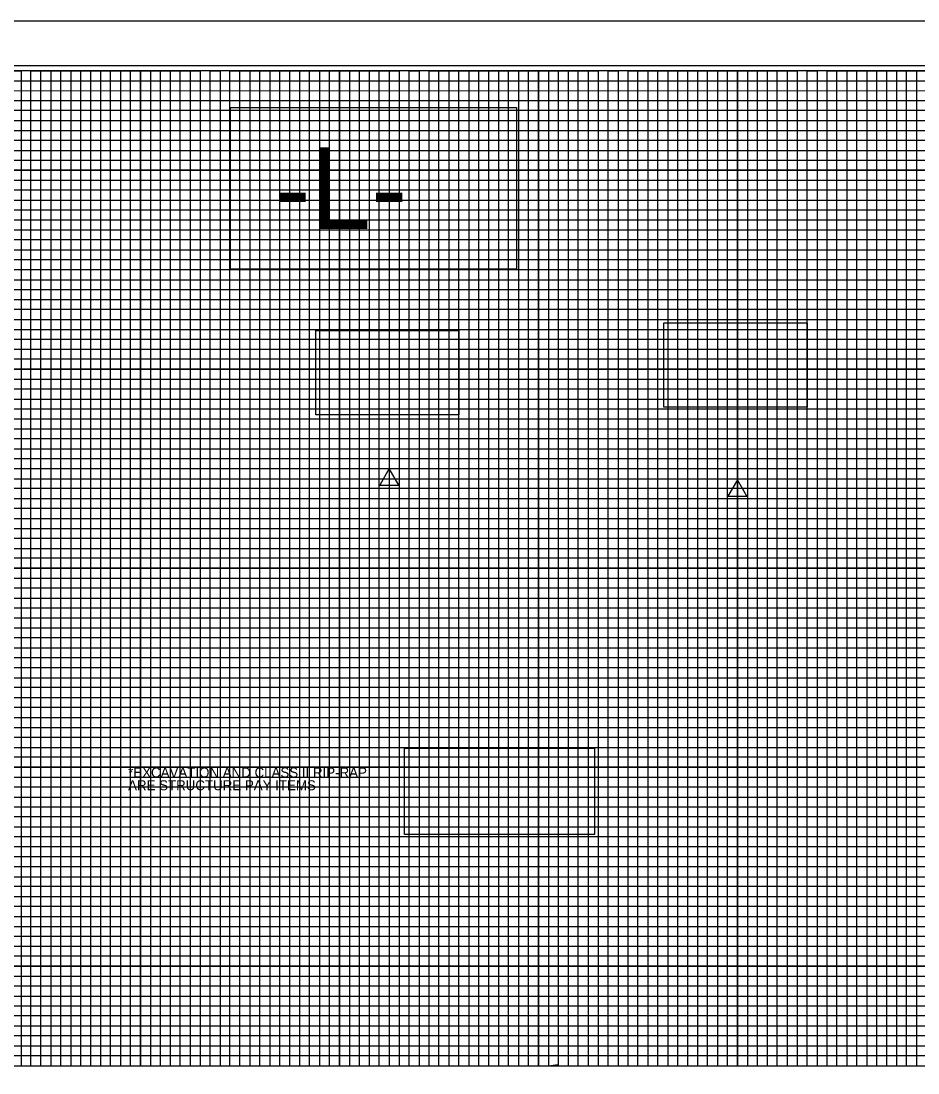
# Model space of a CAD drawing. Extents: x 1019474 to 1021161, y 504129 to 505324.
# Drawn here: x 1020231 to 1020682, y 504701 to 505229 of the extents above; entities that cross this region are included whole.
import ezdxf

# ---------------------------------------------------------------- set-up
doc = ezdxf.new("R2010")
doc.units = 0
for name, color, linetype in [('Default', 7, 'Continuous'), ('Prop Grid Mask', 7, 'Continuous'), ('Prop Vertical Profile Curve Label', 7, 'Continuous'), ('Prop VPI Label', 7, 'Continuous'), ('Sheet Cutting Line CELL', 7, 'Continuous'), ('Sheet DOT Grid CELL', 7, 'Continuous'), ('Sheet Layout Profile Border Port 1', 7, 'Continuous'), ('Sheet Plot Border Inside CELL', 7, 'Continuous'), ('Sheet Plot Border Outside CELL', 7, 'Continuous'), ('Sheet Profile CELL', 7, 'Continuous'), ('Sheet Profile Grid Major CELL', 7, 'Continuous'), ('Sheet Profile Grid Middle CELL', 7, 'Continuous'), ('Sheet Profile Grid Minor CELL', 7, 'Continuous')]:
    doc.layers.add(name, color=color, linetype=linetype)

msp = doc.modelspace()

# ---------------------------------------------------------------- linework, layer by layer
at = {"layer": 'Prop Grid Mask'}
for points in [[(1020336.48, 505185.85), (1020480.21, 505185.85), (1020480.21, 505104.52), (1020336.48, 505104.52)], [(1020554.29, 505077.6), (1020626.17, 505077.6), (1020626.17, 505035.2), (1020554.29, 505035.2)], [(1020379.39, 505073.78), (1020451.27, 505073.78), (1020451.27, 505031.38), (1020379.39, 505031.38)], [(1020423.98, 504863.83), (1020519.35, 504863.83), (1020519.35, 504820.42), (1020423.98, 504820.42)]]:
    msp.add_lwpolyline(points, close=True, dxfattribs=at)
at = {"layer": 'Prop Vertical Profile Curve Label'}
for points in [[(1020411.46, 504996.11), (1020420.98, 504996.11), (1020416.22, 505004.36)], [(1020586.46, 504990.55), (1020595.98, 504990.55), (1020591.22, 504998.8)]]:
    msp.add_lwpolyline(points, close=True, dxfattribs=at)
at = {"layer": 'Sheet Cutting Line CELL'}
msp.add_line((1021158.22, 505229.29), (1019474.22, 505229.29), dxfattribs=at)
at = {"layer": 'Sheet DOT Grid CELL'}
for p, q in [((1020241.22, 504704.29), (1020241.22, 505204.29)), ((1020291.22, 504704.29), (1020291.22, 505204.29)), ((1020341.22, 504704.29), (1020341.22, 505204.29)), ((1020391.22, 504704.29), (1020391.22, 505204.29)), ((1020441.22, 504704.29), (1020441.22, 505204.29)), ((1020491.22, 504704.29), (1020491.22, 505204.29)), ((1020541.22, 504704.29), (1020541.22, 505204.29)), ((1020591.22, 504704.29), (1020591.22, 505204.29)), ((1020641.22, 504704.29), (1020641.22, 505204.29)), ((1020941.17, 505154.29), (1019641.22, 505154.29)), ((1020941.17, 505104.29), (1019641.22, 505104.29)), ((1020941.22, 505054.29), (1019641.22, 505054.29)), ((1021141.22, 505004.29), (1019641.22, 505004.29)), ((1021141.22, 504954.29), (1019641.22, 504954.29)), ((1021141.22, 504904.29), (1019641.22, 504904.29)), ((1021141.22, 504854.29), (1019641.22, 504854.29)), ((1021141.22, 504804.29), (1019641.22, 504804.29)), ((1021141.22, 504754.29), (1019641.22, 504754.29))]:
    msp.add_line(p, q, dxfattribs=at)
at = {"layer": 'Sheet Layout Profile Border Port 1'}
msp.add_lwpolyline([(1019691.22, 505043.24), (1019691.22, 504704.29), (1021091.22, 504704.29), (1021091.22, 505043.24)], dxfattribs=at)
at = {"layer": 'Sheet Plot Border Inside CELL'}
msp.add_lwpolyline([(1019487.22, 504151.74), (1021153.72, 504151.74), (1021153.72, 505206.84), (1019487.22, 505206.84)], close=True, dxfattribs=at)
at = {"layer": 'Sheet Plot Border Outside CELL'}
msp.add_lwpolyline([(1019474.22, 504129.29), (1021158.22, 504129.29), (1021158.22, 505229.29), (1019474.22, 505229.29)], close=True, dxfattribs=at)
at = {"layer": 'Sheet Profile CELL'}
msp.add_line((1019641.22, 504704.29), (1021141.22, 504704.29), dxfattribs=at)
msp.add_lwpolyline([(1021141.22, 505204.29), (1019641.22, 505204.29), (1019641.22, 504154.29), (1021141.22, 504154.29)], close=True, dxfattribs=at)
at = {"layer": 'Sheet Profile Grid Major CELL'}
for points in [[(1020191.22, 504704.29), (1020241.22, 504704.29), (1020241.22, 505204.29), (1020291.22, 505204.29), (1020291.22, 504704.29), (1020341.22, 504704.29), (1020341.22, 505204.29), (1020391.22, 505204.29), (1020391.22, 504704.29), (1020441.22, 504704.29), (1020441.22, 505204.29), (1020491.22, 505204.29), (1020491.22, 504704.29), (1020541.22, 504704.29), (1020541.22, 505204.29), (1020591.22, 505204.29), (1020591.22, 504704.29), (1020641.22, 504704.29), (1020641.22, 505204.29), (1020691.22, 505204.29)], [(1019641.22, 505154.29), (1020941.22, 505154.29)], [(1020941.22, 505104.29), (1019641.22, 505104.29), (1019641.22, 505054.29), (1020941.22, 505054.29)], [(1021141.22, 505004.29), (1019641.22, 505004.29), (1019641.22, 504954.29), (1021141.22, 504954.29)], [(1021141.22, 504904.29), (1019641.22, 504904.29), (1019641.22, 504854.29), (1021141.22, 504854.29)], [(1021141.22, 504804.29), (1019641.22, 504804.29), (1019641.22, 504804.29), (1019641.22, 504754.29), (1021141.22, 504754.29)]]:
    msp.add_lwpolyline(points, dxfattribs=at)
at = {"layer": 'Sheet Profile Grid Middle CELL'}
msp.add_line((1019641.22, 505179.29), (1020941.17, 505179.29), dxfattribs=at)
for points in [[(1020216.22, 504704.29), (1020266.22, 504704.29), (1020266.22, 504704.29), (1020266.22, 505204.29), (1020316.22, 505204.29), (1020316.22, 504704.29), (1020366.22, 504704.29), (1020366.22, 505204.29), (1020416.22, 505204.29), (1020416.22, 504704.29), (1020466.22, 504704.29), (1020466.22, 505204.29), (1020516.22, 505204.29), (1020516.22, 504704.29), (1020566.22, 504704.29), (1020566.22, 505204.29), (1020616.22, 505204.29), (1020616.22, 504704.29), (1020666.22, 504704.29), (1020666.22, 505204.29), (1020716.22, 505204.29)], [(1020941.22, 505129.29), (1019641.22, 505129.29), (1019641.22, 505079.29), (1020941.22, 505079.29)], [(1021141.22, 505029.29), (1019641.22, 505029.29), (1019641.22, 504979.29), (1020966.22, 504979.29)], [(1021141.22, 504929.29), (1019641.22, 504929.29), (1019641.22, 504879.29), (1021141.22, 504879.29)], [(1021141.22, 504829.29), (1019641.22, 504829.29), (1019641.22, 504779.29), (1021141.22, 504779.29)], [(1021141.22, 504729.29), (1019641.22, 504729.29)]]:
    msp.add_lwpolyline(points, dxfattribs=at)
at = {"layer": 'Sheet Profile Grid Minor CELL'}
for p, q in [((1019691.22, 505199.29), (1020941.22, 505199.29)), ((1020941.22, 505194.29), (1019691.22, 505193.94)), ((1019691.22, 505189.29), (1020941.22, 505189.29)), ((1020941.17, 505069.29), (1019691.22, 505069.29)), ((1020941.22, 505064.29), (1019691.22, 505064.29)), ((1020941.22, 505059.29), (1019691.22, 505059.29)), ((1019691.22, 505049.29), (1020941.22, 505049.29)), ((1020941.22, 505044.29), (1019691.22, 505044.29)), ((1019691.22, 505039.29), (1021091.22, 505039.29)), ((1021091.22, 505019.29), (1019691.22, 505019.29)), ((1019691.22, 505014.29), (1021091.22, 505014.29)), ((1021091.22, 504994.29), (1019691.22, 504994.29)), ((1019691.22, 504989.29), (1021091.22, 504989.29)), ((1021091.22, 504969.29), (1019691.22, 504969.29)), ((1019691.22, 504964.29), (1021091.22, 504964.29)), ((1021091.22, 504959.29), (1019691.22, 504959.29)), ((1019691.22, 504949.29), (1021091.22, 504949.29)), ((1021091.22, 504944.29), (1019691.22, 504944.29)), ((1019691.22, 504939.29), (1021091.22, 504939.29)), ((1021091.22, 504934.29), (1019691.22, 504934.29)), ((1019691.22, 504924.29), (1021091.22, 504924.29)), ((1021091.22, 504919.29), (1019691.22, 504919.29)), ((1019691.22, 504914.29), (1021091.22, 504914.29)), ((1021091.22, 504909.29), (1019691.22, 504909.29)), ((1019691.22, 504899.29), (1021091.22, 504899.29)), ((1021091.22, 504894.29), (1019691.22, 504894.29)), ((1019691.22, 504889.29), (1021091.22, 504889.29)), ((1021091.22, 504884.29), (1019691.22, 504884.29)), ((1019691.22, 504874.29), (1021091.22, 504874.29)), ((1021091.22, 504869.29), (1019691.22, 504869.29)), ((1019691.22, 504864.29), (1021091.22, 504864.29)), ((1021091.22, 504859.29), (1019691.22, 504859.29)), ((1019691.22, 504849.29), (1021091.22, 504849.29)), ((1021091.22, 504844.29), (1019691.22, 504844.29)), ((1019691.22, 504839.29), (1021091.22, 504839.29)), ((1021091.22, 504834.29), (1019691.22, 504834.29)), ((1019691.22, 504824.29), (1021091.22, 504824.29)), ((1021091.22, 504819.29), (1019691.22, 504819.29)), ((1021091.22, 504814.29), (1019691.22, 504814.29)), ((1021091.22, 504809.29), (1019691.22, 504809.29)), ((1019691.22, 504799.29), (1021091.22, 504799.29)), ((1021091.22, 504794.29), (1019691.22, 504794.29)), ((1019691.22, 504789.29), (1021091.22, 504789.29)), ((1021091.22, 504784.29), (1019691.22, 504784.29)), ((1019691.22, 504774.29), (1021091.22, 504774.29)), ((1021091.22, 504769.29), (1019691.22, 504769.29)), ((1019691.22, 504764.29), (1021091.22, 504764.29)), ((1021091.22, 504759.29), (1019691.22, 504759.29)), ((1019691.22, 504749.29), (1021091.22, 504749.29)), ((1021091.22, 504744.29), (1019691.22, 504744.29)), ((1019691.22, 504739.29), (1021091.22, 504739.29)), ((1021091.22, 504734.29), (1019691.22, 504734.29)), ((1019691.22, 504724.29), (1021091.22, 504724.29)), ((1021091.22, 504719.29), (1019691.22, 504719.29)), ((1019691.22, 504714.29), (1021091.22, 504714.29))]:
    msp.add_line(p, q, dxfattribs=at)
for points in [[(1020226.22, 505204.29), (1020231.22, 505204.29), (1020231.22, 504704.29), (1020236.22, 504704.29), (1020236.22, 505204.29), (1020246.22, 505204.29), (1020246.22, 504704.29), (1020251.22, 504704.29), (1020251.22, 505204.29), (1020256.22, 505204.29), (1020256.22, 504704.29), (1020261.22, 504704.29), (1020261.22, 505204.29), (1020271.22, 505204.29), (1020271.22, 504704.29), (1020276.22, 504704.29), (1020276.22, 505204.29), (1020281.22, 505204.29), (1020281.22, 504704.29), (1020286.22, 504704.29), (1020286.22, 505204.29), (1020296.22, 505204.29), (1020296.22, 504704.29), (1020301.22, 504704.29), (1020301.22, 505204.29), (1020306.22, 505204.29), (1020306.22, 504704.29), (1020311.22, 504704.29), (1020311.22, 505204.29), (1020321.22, 505204.29), (1020321.22, 504704.29), (1020326.22, 504704.29), (1020326.22, 505204.29), (1020331.22, 505204.29), (1020331.22, 504704.29), (1020336.22, 504704.29), (1020336.22, 505204.29), (1020346.22, 505204.29), (1020346.22, 504704.29), (1020346.22, 504704.29), (1020351.22, 504704.29), (1020351.22, 505204.29), (1020356.22, 505204.29), (1020356.22, 504704.29), (1020361.22, 504704.29), (1020361.22, 505204.29), (1020371.22, 505204.29), (1020371.22, 504704.29), (1020376.22, 504704.29), (1020376.22, 505204.29), (1020381.22, 505204.29), (1020381.22, 504704.29), (1020386.22, 504704.29), (1020386.22, 505204.29), (1020396.22, 505204.29), (1020396.22, 504704.29), (1020401.22, 504704.29), (1020401.22, 505204.29), (1020406.22, 505204.29), (1020406.22, 504704.29), (1020411.22, 504704.29), (1020411.22, 505204.29), (1020421.22, 505204.29), (1020421.22, 504704.29), (1020426.22, 504704.29), (1020426.22, 505204.29), (1020431.22, 505204.29), (1020431.22, 504704.29), (1020436.22, 504704.29), (1020436.22, 505204.29), (1020446.22, 505204.29), (1020446.22, 504704.29), (1020451.22, 504704.29), (1020451.22, 505204.29), (1020456.22, 505204.29), (1020456.22, 504704.29), (1020461.22, 504704.29), (1020461.22, 505204.29), (1020471.22, 505204.29), (1020471.22, 504704.29), (1020476.22, 504704.29), (1020476.22, 505204.29), (1020481.22, 505204.29), (1020481.22, 504704.29), (1020486.22, 504704.29), (1020486.22, 505204.29), (1020496.22, 505204.29), (1020496.22, 504704.29), (1020500.92, 504704.84), (1020501.22, 504704.29), (1020501.22, 505204.29), (1020506.22, 505204.29), (1020506.22, 504704.29), (1020511.22, 504704.29), (1020511.22, 505204.29), (1020521.22, 505204.29), (1020521.22, 504704.29), (1020526.22, 504704.29)], [(1020526.22, 504704.29), (1020526.22, 505204.29), (1020531.22, 505204.29), (1020531.22, 504704.29), (1020536.22, 504704.29), (1020536.22, 505204.29), (1020546.22, 505204.29), (1020546.22, 504704.29), (1020551.22, 504704.29), (1020551.22, 505204.29), (1020556.22, 505204.29), (1020556.22, 504704.29), (1020561.22, 504704.29), (1020561.22, 505204.29), (1020571.22, 505204.29), (1020571.22, 504704.29), (1020576.22, 504704.29), (1020576.22, 505204.29), (1020581.22, 505204.29), (1020581.22, 504704.29), (1020586.22, 504704.29), (1020586.22, 505204.29), (1020596.22, 505204.29), (1020596.22, 504704.29), (1020601.22, 504704.29), (1020601.22, 505204.29), (1020606.22, 505204.29), (1020606.22, 504704.29), (1020611.22, 504704.29), (1020611.22, 505204.29), (1020621.22, 505204.29), (1020621.22, 504704.29), (1020626.22, 504704.29), (1020626.22, 505204.29), (1020631.22, 505204.29), (1020631.22, 504704.29), (1020636.22, 504704.29), (1020636.22, 505204.29), (1020646.22, 505204.29), (1020646.22, 504704.29), (1020651.22, 504704.29), (1020651.22, 505204.29), (1020656.22, 505204.29), (1020656.22, 504704.29), (1020661.22, 504704.29), (1020661.22, 505204.29), (1020671.22, 505204.29), (1020671.22, 504704.29), (1020676.22, 504704.29), (1020676.22, 505204.29), (1020681.22, 505204.29), (1020681.22, 504704.29), (1020686.22, 504704.29)], [(1020941.22, 505184.29), (1019691.22, 505184.29), (1019691.22, 505174.29), (1020941.22, 505174.29)], [(1020941.17, 505169.29), (1019691.22, 505169.29), (1019691.22, 505164.29), (1020941.22, 505164.29)], [(1020941.22, 505159.29), (1019691.22, 505159.29), (1019691.22, 505149.29), (1020941.22, 505149.29)], [(1020941.22, 505144.29), (1019691.22, 505144.29), (1019691.22, 505139.29), (1020941.22, 505139.29)], [(1020941.22, 505134.29), (1019691.22, 505134.29), (1019691.22, 505124.29), (1020941.22, 505124.29)], [(1020941.22, 505119.29), (1019691.22, 505119.29), (1019691.22, 505114.29), (1020941.22, 505114.29)], [(1020941.22, 505109.29), (1019691.22, 505109.29), (1019691.22, 505099.29), (1020941.22, 505099.29)], [(1020941.22, 505094.19), (1019691.32, 505094.19), (1019691.32, 505089.29), (1020941.22, 505089.29)], [(1020941.22, 505084.29), (1019691.22, 505084.29), (1019691.22, 505074.29), (1020941.22, 505074.29)], [(1021091.22, 505034.29), (1019691.22, 505034.29), (1019691.22, 505024.29), (1021091.22, 505024.29)], [(1021091.22, 505009.29), (1019691.22, 505009.29), (1019691.22, 504999.29), (1021091.22, 504999.29)], [(1021091.22, 504984.29), (1019691.22, 504984.29), (1019691.22, 504974.29), (1021091.22, 504974.29)], [(1021091.22, 504709.29), (1019691.22, 504709.29)]]:
    msp.add_lwpolyline(points, dxfattribs=at)

# ---------------------------------------------------------------- texts
at = {"layer": 'Default'}
for s, p in [('*EXCAVATION AND CLASS II RIP-RAP', (1020285.02, 504849.16)), ('ARE STRUCTURE PAY ITEMS', (1020285.02, 504842.73))]:
    msp.add_text(s, height=5, rotation=360, dxfattribs=at).set_placement(p)
at = {"layer": 'Prop VPI Label'}
msp.add_text('-L-', height=40.95, dxfattribs=at).set_placement((1020358.39, 505124.83))

doc.saveas('drawing.dxf')
